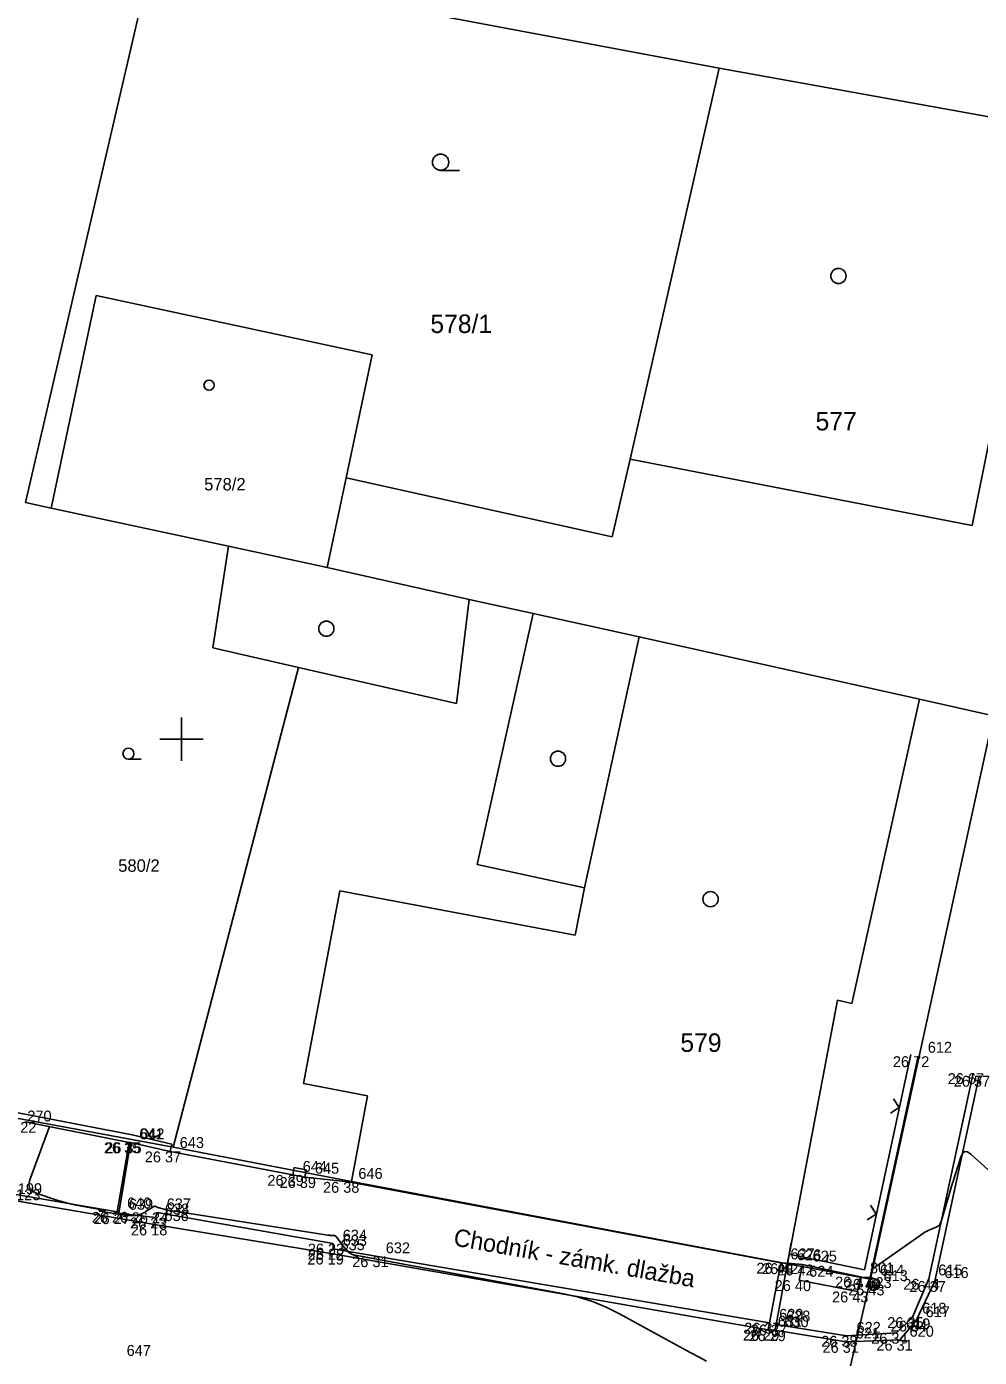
# Model space of a CAD drawing. Extents: x -702257 to -701487, y -1009871 to -1008841.
# Drawn here: x -701728.56 to -701706.64, y -1009389.21 to -1009358.61 of the extents above; entities that cross this region are included whole.
import ezdxf

# ---------------------------------------------------------------- set-up
doc = ezdxf.new("R2010")
doc.units = 0
for name, color, linetype in [('Ex_Minor Contours', 7, 'Continuous'), ('Z_body', 7, 'Continuous'), ('Z_body_cisla', 7, 'Continuous'), ('Z_body_vysky_redukovane', 7, 'Continuous'), ('Z_budova', 7, 'Continuous'), ('Z_hektometricka_sit', 7, 'Continuous'), ('Z_katastr_cisla_pozemkova', 7, 'Continuous'), ('Z_katastr_cisla_stavebni', 7, 'Continuous'), ('Z_katastr_hranice', 7, 'Continuous'), ('Z_katastr_vnitrni_kresba', 7, 'Continuous'), ('Z_katastr_znacky_budov', 7, 'Continuous'), ('Z_katastr_znacky_kultur', 7, 'Continuous'), ('Z_komunikace', 7, 'Continuous'), ('Z_obruba', 7, 'Continuous'), ('Z_pilire', 7, 'Continuous'), ('Z_ploty', 7, 'Continuous'), ('Z_ploty_znacky', 7, 'Continuous'), ('Z_popisy', 7, 'Continuous'), ('Z_sloupy', 7, 'Continuous'), ('Z_vstupy', 7, 'Continuous'), ('Z_zlabek', 7, 'Continuous')]:
    doc.layers.add(name, color=color, linetype=linetype)

# ---------------------------------------------------------------- blocks, each defined once
blk = doc.blocks.new('POINT_DISPLAY')
blk.add_line((0, 0), (0, 0))
blk = doc.blocks.new('Z210')
blk.add_line((0, 0), (0, 0.17))
blk = doc.blocks.new('Z212')
for p, q in [((-0.17, 0.17), (0, 0)), ((0, 0), (0.17, 0.17))]:
    blk.add_line(p, q)
blk = doc.blocks.new('Z601')
for p, q in [((-0.13, 0.03), (-0.1, 0.08)), ((-0.13, -0.03), (-0.13, 0.03)), ((-0.1, 0.08), (-0.08, 0.1)), ((-0.08, 0.1), (-0.03, 0.13)), ((-0.08, 0.05), (-0.08, -0.05)), ((-0.03, 0.13), (0.03, 0.13)), ((-0.03, -0.08), (-0.03, 0.08)), ((-0.03, 0.08), (0.03, 0.08)), ((0.03, 0.13), (0.08, 0.1)), ((0.03, 0.08), (0.03, -0.08)), ((0.08, 0.1), (0.1, 0.08)), ((0.08, -0.05), (0.08, 0.05)), ((0.1, 0.08), (0.13, 0.03)), ((0.13, 0.03), (0.13, -0.03)), ((-0.1, -0.08), (-0.13, -0.03)), ((-0.08, -0.1), (-0.1, -0.08)), ((-0.08, -0.05), (-0.03, -0.08)), ((-0.03, -0.13), (-0.08, -0.1)), ((0.03, -0.13), (-0.03, -0.13)), ((0.03, -0.08), (0.08, -0.05)), ((0.08, -0.1), (0.03, -0.13)), ((0.1, -0.08), (0.08, -0.1)), ((0.13, -0.03), (0.1, -0.08))]:
    blk.add_line(p, q)

msp = doc.modelspace()

# ---------------------------------------------------------------- linework, layer by layer
at = {"layer": 'Ex_Minor Contours'}
for points in [[(-701712.923, -1009389.301), (-701713.104, -1009389.206), (-701713.284, -1009389.11), (-701713.463, -1009389.012), (-701714.919, -1009388.212), (-701715.226, -1009388.059), (-701715.542, -1009387.932), (-701715.868, -1009387.83), (-701716.202, -1009387.755), (-701721.005, -1009386.867), (-701721.025, -1009386.863), (-701721.044, -1009386.857), (-701721.062, -1009386.849), (-701721.08, -1009386.839), (-701721.155, -1009386.794), (-701721.169, -1009386.785), (-701721.181, -1009386.774), (-701721.193, -1009386.763), (-701721.204, -1009386.751), (-701721.245, -1009386.699), (-701721.255, -1009386.685), (-701721.265, -1009386.672), (-701721.275, -1009386.659), (-701721.285, -1009386.646), (-701721.444, -1009386.436), (-701721.454, -1009386.425), (-701721.467, -1009386.417), (-701721.48, -1009386.412), (-701721.495, -1009386.41), (-701721.582, -1009386.409), (-701721.591, -1009386.408), (-701721.6, -1009386.407), (-701721.626, -1009386.403), (-701721.635, -1009386.401), (-701725.305, -1009385.83), (-701725.328, -1009385.826), (-701725.352, -1009385.821), (-701725.375, -1009385.816), (-701725.398, -1009385.81), (-701725.516, -1009385.778), (-701725.526, -1009385.775), (-701725.537, -1009385.771), (-701725.547, -1009385.767), (-701725.557, -1009385.763), (-701725.596, -1009385.743), (-701725.606, -1009385.74), (-701725.615, -1009385.739), (-701725.625, -1009385.741), (-701725.634, -1009385.745), (-701725.816, -1009385.863), (-701725.835, -1009385.874), (-701725.854, -1009385.885), (-701725.874, -1009385.894), (-701725.895, -1009385.903), (-701725.978, -1009385.934), (-701725.999, -1009385.941), (-701726.021, -1009385.946), (-701726.042, -1009385.95), (-701726.065, -1009385.951), (-701726.198, -1009385.956), (-701726.228, -1009385.956), (-701726.258, -1009385.955), (-701726.287, -1009385.952), (-701726.316, -1009385.948), (-701726.878, -1009385.85), (-701726.894, -1009385.846), (-701726.9, -1009385.844), (-701726.894, -1009385.842), (-701726.877, -1009385.842), (-701726.788, -1009385.841), (-701726.771, -1009385.841), (-701726.765, -1009385.839), (-701726.771, -1009385.836), (-701726.787, -1009385.833), (-701727.42, -1009385.713), (-701727.532, -1009385.69), (-701727.643, -1009385.663), (-701727.753, -1009385.632), (-701727.863, -1009385.597), (-701728.341, -1009385.438), (-701728.437, -1009385.39), (-701728.494, -1009385.323), (-701728.511, -1009385.237), (-701728.488, -1009385.131), (-701728.038, -1009383.908)], [(-701706.207, -1009385.118), (-701706.84, -1009384.544), (-701706.917, -1009384.491), (-701706.982, -1009384.484), (-701707.034, -1009384.523), (-701707.074, -1009384.608), (-701707.208, -1009385.039), (-701707.241, -1009385.147), (-701707.274, -1009385.255), (-701707.306, -1009385.363), (-701707.338, -1009385.471), (-701707.52, -1009386.093), (-701707.535, -1009386.132), (-701707.558, -1009386.164), (-701707.587, -1009386.19), (-701707.623, -1009386.21), (-701707.782, -1009386.279), (-701707.821, -1009386.297), (-701707.859, -1009386.317), (-701707.896, -1009386.339), (-701707.932, -1009386.362), (-701709.112, -1009387.187)]]:
    msp.add_lwpolyline(points, dxfattribs=at)
at = {"layer": 'Z_budova'}
for p, q in [((-701711.21, -1009387.04), (-701721.16, -1009385.18)), ((-701710.97, -1009386.58), (-701711.06, -1009387.05)), ((-701711.06, -1009387.05), (-701711.21, -1009387.04))]:
    msp.add_line(p, q, dxfattribs=at)
at = {"layer": 'Z_hektometricka_sit'}
for p, q in [((-701725, -1009374.5), (-701725, -1009375.5)), ((-701725, -1009374.5), (-701725, -1009375.5)), ((-701725, -1009374.5), (-701725, -1009375.5)), ((-701725.5, -1009375), (-701724.5, -1009375)), ((-701725.5, -1009375), (-701724.5, -1009375)), ((-701725.5, -1009375), (-701724.5, -1009375))]:
    msp.add_line(p, q, dxfattribs=at)
at = {"layer": 'Z_katastr_hranice'}
for p, q in [((-701728.59, -1009369.56), (-701725.71, -1009357.15)), ((-701720.37, -1009358.12), (-701712.63, -1009359.57)), ((-701712.63, -1009359.57), (-701714.68, -1009368.56)), ((-701712.63, -1009359.57), (-701705.18, -1009360.91)), ((-701728, -1009369.69), (-701726.96, -1009364.8)), ((-701726.96, -1009364.8), (-701720.61, -1009366.16)), ((-701720.61, -1009366.16), (-701721.21, -1009368.99)), ((-701714.68, -1009368.56), (-701715.09, -1009370.35)), ((-701721.21, -1009368.99), (-701721.65, -1009371.05)), ((-701715.09, -1009370.35), (-701721.21, -1009368.99)), ((-701728.59, -1009369.56), (-701728, -1009369.69)), ((-701723.92, -1009370.56), (-701728, -1009369.69)), ((-701723.92, -1009370.56), (-701724.28, -1009372.9)), ((-701721.65, -1009371.05), (-701723.92, -1009370.56)), ((-701721.65, -1009371.05), (-701718.38, -1009371.79)), ((-701718.38, -1009371.79), (-701716.91, -1009372.11)), ((-701716.91, -1009372.11), (-701714.47, -1009372.65)), ((-701714.47, -1009372.65), (-701708.02, -1009374.08)), ((-701724.28, -1009372.9), (-701722.31, -1009373.35)), ((-701722.31, -1009373.35), (-701725.19, -1009384.38)), ((-701708.02, -1009374.08), (-701706.32, -1009374.46)), ((-701709.15, -1009387.42), (-701706.32, -1009374.46)), ((-701731.72, -1009383.17), (-701725.19, -1009384.38)), ((-701725.19, -1009384.38), (-701721.09, -1009385.17)), ((-701721.09, -1009385.17), (-701711.06, -1009387.06)), ((-701711.06, -1009387.06), (-701709.15, -1009387.42)), ((-701709.15, -1009387.42), (-701711.4, -1009397.2))]:
    msp.add_line(p, q, dxfattribs=at)
at = {"layer": 'Z_katastr_vnitrni_kresba'}
for p, q in [((-701706.81, -1009370.09), (-701705.82, -1009365.14)), ((-701714.68, -1009368.56), (-701706.81, -1009370.09)), ((-701718.38, -1009371.79), (-701718.67, -1009374.18)), ((-701718.2, -1009377.88), (-701716.91, -1009372.11)), ((-701714.47, -1009372.65), (-701715.73, -1009378.42)), ((-701718.67, -1009374.18), (-701722.31, -1009373.35)), ((-701708.02, -1009374.08), (-701709.58, -1009381.08)), ((-701715.73, -1009378.42), (-701718.2, -1009377.88)), ((-701715.94, -1009379.51), (-701715.73, -1009378.42)), ((-701721.36, -1009378.49), (-701722.19, -1009382.92)), ((-701721.36, -1009378.49), (-701715.94, -1009379.51)), ((-701709.91, -1009381), (-701711.06, -1009387.06)), ((-701709.58, -1009381.08), (-701709.91, -1009381)), ((-701722.19, -1009382.92), (-701720.72, -1009383.2)), ((-701720.72, -1009383.2), (-701721.09, -1009385.17))]:
    msp.add_line(p, q, dxfattribs=at)
at = {"layer": 'Z_katastr_znacky_budov'}
for centre, radius in [((-701709.887, -1009364.349), 0.175), ((-701724.365, -1009366.859), 0.117), ((-701721.667, -1009372.459), 0.175), ((-701716.337, -1009375.449), 0.175), ((-701712.827, -1009378.679), 0.175)]:
    msp.add_circle(centre, radius, dxfattribs=at)
at = {"layer": 'Z_katastr_znacky_kultur'}
for p, q in [((-701719.038, -1009361.92), (-701718.601, -1009361.92)), ((-701726.219, -1009375.46), (-701725.926, -1009375.46))]:
    msp.add_line(p, q, dxfattribs=at)
for centre, radius in [((-701719.038, -1009361.732), 0.187), ((-701726.219, -1009375.334), 0.126)]:
    msp.add_circle(centre, radius, dxfattribs=at)
at = {"layer": 'Z_komunikace'}
for p, q in [((-701706.65, -1009382.74), (-701707.67, -1009387.46)), ((-701728.85, -1009385.61), (-701725.62, -1009386.16)), ((-701721.56, -1009386.83), (-701725.62, -1009386.16)), ((-701711.5, -1009388.58), (-701721.56, -1009386.83)), ((-701707.67, -1009387.46), (-701708.1, -1009388.37)), ((-701708.1, -1009388.37), (-701708.47, -1009388.81)), ((-701711.35, -1009388.59), (-701711.5, -1009388.58)), ((-701709.71, -1009388.86), (-701711.35, -1009388.59)), ((-701708.47, -1009388.81), (-701709.71, -1009388.86))]:
    msp.add_line(p, q, dxfattribs=at)
at = {"layer": 'Z_obruba'}
for p, q in [((-701706.79, -1009382.68), (-701707.81, -1009387.41)), ((-701726.2, -1009384.27), (-701726.48, -1009385.87)), ((-701726.44, -1009385.9), (-701726.17, -1009384.27)), ((-701728.81, -1009385.47), (-701726.48, -1009385.87)), ((-701726.44, -1009385.9), (-701726.48, -1009385.87)), ((-701725.6, -1009386), (-701726.44, -1009385.9)), ((-701725.56, -1009385.88), (-701725.6, -1009386)), ((-701721.51, -1009386.6), (-701725.56, -1009385.88)), ((-701721.51, -1009386.72), (-701721.51, -1009386.6)), ((-701720.53, -1009386.89), (-701721.51, -1009386.72)), ((-701711.47, -1009388.42), (-701720.53, -1009386.89)), ((-701707.81, -1009387.41), (-701708.18, -1009388.29)), ((-701709.7, -1009388.72), (-701711.32, -1009388.46)), ((-701708.18, -1009388.29), (-701708.55, -1009388.65)), ((-701708.55, -1009388.65), (-701709.7, -1009388.72))]:
    msp.add_line(p, q, dxfattribs=at)
at = {"layer": 'Z_pilire'}
for p, q in [((-701710.79, -1009387.44), (-701710.71, -1009387.08)), ((-701710.79, -1009387.44), (-701709.45, -1009387.7)), ((-701709.45, -1009387.7), (-701709.38, -1009387.36))]:
    msp.add_line(p, q, dxfattribs=at)
at = {"layer": 'Z_ploty'}
for p, q in [((-701728.558, -1009383.628), (-701740.738, -1009381.358)), ((-701708.22, -1009382.25), (-701709.29, -1009387.2)), ((-701708.05, -1009382.29), (-701709.16, -1009387.41)), ((-701728.558, -1009383.628), (-701726.13, -1009384.1)), ((-701728.59, -1009383.8), (-701726.2, -1009384.27)), ((-701726.2, -1009384.27), (-701726.17, -1009384.27)), ((-701726.17, -1009384.27), (-701725.26, -1009384.48)), ((-701726.13, -1009384.1), (-701725.22, -1009384.31)), ((-701725.26, -1009384.48), (-701725.22, -1009384.31)), ((-701722.44, -1009385.02), (-701722.41, -1009384.85)), ((-701722.41, -1009384.85), (-701722.13, -1009384.9)), ((-701722.44, -1009385.02), (-701722.16, -1009385.07)), ((-701722.16, -1009385.07), (-701722.13, -1009384.9)), ((-701711.02, -1009386.84), (-701709.29, -1009387.2)), ((-701711.06, -1009387.05), (-701710.71, -1009387.08)), ((-701710.71, -1009387.08), (-701709.38, -1009387.36)), ((-701709.38, -1009387.36), (-701709.16, -1009387.41))]:
    msp.add_line(p, q, dxfattribs=at)
at = {"layer": 'Z_vstupy'}
for p, q in [((-701725.26, -1009384.48), (-701722.44, -1009385.02)), ((-701722.16, -1009385.07), (-701721.16, -1009385.18))]:
    msp.add_line(p, q, dxfattribs=at)
at = {"layer": 'Z_zlabek'}
for p, q in [((-701711.47, -1009388.42), (-701711.21, -1009387.04)), ((-701711.06, -1009387.05), (-701711.32, -1009388.46)), ((-701711.5, -1009388.58), (-701711.47, -1009388.42)), ((-701711.32, -1009388.46), (-701711.35, -1009388.59))]:
    msp.add_line(p, q, dxfattribs=at)

# ---------------------------------------------------------------- block references
at = {"layer": 'Z_body'}
for p in [(-701708.05, -1009382.29), (-701706.79, -1009382.68), (-701706.65, -1009382.74), (-701726.2, -1009384.27), (-701726.17, -1009384.27), (-701725.26, -1009384.48), (-701722.44, -1009385.02), (-701722.16, -1009385.07), (-701721.16, -1009385.18), (-701726.48, -1009385.87), (-701726.44, -1009385.9), (-701725.6, -1009386), (-701725.56, -1009385.88), (-701725.62, -1009386.16), (-701721.51, -1009386.6), (-701721.51, -1009386.72), (-701721.56, -1009386.83), (-701720.53, -1009386.89), (-701711.21, -1009387.04), (-701711.06, -1009387.05), (-701710.71, -1009387.08), (-701710.79, -1009387.44), (-701709.38, -1009387.36), (-701709.16, -1009387.41), (-701709.08, -1009387.54), (-701707.81, -1009387.41), (-701707.67, -1009387.46), (-701709.45, -1009387.7), (-701711.47, -1009388.42), (-701711.32, -1009388.46), (-701708.18, -1009388.29), (-701708.1, -1009388.37), (-701711.5, -1009388.58), (-701711.35, -1009388.59), (-701709.71, -1009388.86), (-701709.7, -1009388.72), (-701708.55, -1009388.65), (-701708.47, -1009388.81)]:
    msp.add_blockref('POINT_DISPLAY', p, dxfattribs=at)
at = {"layer": 'Z_ploty_znacky'}
for name, p, rotation in [('Z212', (-701708.49, -1009383.47), 77.8), ('Z212', (-701725.68, -1009384.2), -13.00000000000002), ('Z212', (-701709.02, -1009385.92), 77.8), ('Z210', (-701710.16, -1009387.02), -11.899999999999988)]:
    msp.add_blockref(name, p, dxfattribs=dict(at, rotation=rotation))
at = {"layer": 'Z_sloupy'}
msp.add_blockref('Z601', (-701709.08, -1009387.54), dxfattribs=at)

# ---------------------------------------------------------------- texts
at = {"layer": 'Z_body_cisla'}
for s, p in [('612', (-701707.83, -1009382.21)), ('270', (-701728.545, -1009383.79)), ('641', (-701725.97, -1009384.2)), ('642', (-701725.95, -1009384.2)), ('643', (-701725.04, -1009384.4)), ('644', (-701722.21, -1009384.95)), ('645', (-701721.93, -1009384.99)), ('646', (-701720.93, -1009385.11)), ('123', (-701728.805, -1009385.6)), ('199', (-701728.765, -1009385.46)), ('640', (-701726.25, -1009385.79)), ('639', (-701726.21, -1009385.82)), ('638', (-701725.38, -1009385.93)), ('637', (-701725.34, -1009385.81)), ('636', (-701725.39, -1009386.08)), ('634', (-701721.29, -1009386.53)), ('633', (-701721.29, -1009386.65)), ('635', (-701721.34, -1009386.75)), ('632', (-701720.3, -1009386.82)), ('627', (-701710.99, -1009386.96)), ('626', (-701710.84, -1009386.98)), ('625', (-701710.48, -1009387.01)), ('801', (-701709.16, -1009387.28)), ('624', (-701710.56, -1009387.36)), ('614', (-701708.93, -1009387.33)), ('613', (-701708.85, -1009387.46)), ('615', (-701707.59, -1009387.33)), ('616', (-701707.45, -1009387.39)), ('623', (-701709.22, -1009387.62)), ('631', (-701711.28, -1009388.51)), ('629', (-701711.25, -1009388.35)), ('628', (-701711.09, -1009388.39)), ('618', (-701707.96, -1009388.21)), ('617', (-701707.88, -1009388.29)), ('630', (-701711.13, -1009388.52)), ('621', (-701709.49, -1009388.78)), ('622', (-701709.47, -1009388.65)), ('619', (-701708.33, -1009388.57)), ('620', (-701708.25, -1009388.74)), ('647', (-701726.26, -1009389.18))]:
    msp.add_text(s, height=0.25, dxfattribs=at).set_placement(p)
at = {"layer": 'Z_body_vysky_redukovane'}
for s, p in [('26 72', (-701708.633, -1009382.54)), ('26 67', (-701707.373, -1009382.93)), ('26 57', (-701707.233, -1009382.99)), ('26 22', (-701729.173, -1009384.05)), ('26 35', (-701726.783, -1009384.52)), ('26 35', (-701726.753, -1009384.52)), ('26 37', (-701725.843, -1009384.73)), ('26 39', (-701723.023, -1009385.27)), ('26 39', (-701722.743, -1009385.32)), ('26 38', (-701721.743, -1009385.43)), ('26 26', (-701727.063, -1009386.12)), ('26 27', (-701727.023, -1009386.15)), ('26 23', (-701726.183, -1009386.25)), ('26 24', (-701726.143, -1009386.13)), ('26 18', (-701726.162, -1009386.41)), ('26 23', (-701722.093, -1009386.85)), ('26 22', (-701722.093, -1009386.97)), ('26 19', (-701722.102, -1009387.08)), ('26 31', (-701721.072, -1009387.14)), ('26 40', (-701711.773, -1009387.29)), ('26 42', (-701711.643, -1009387.3)), ('26 42', (-701711.293, -1009387.33)), ('26 40', (-701711.353, -1009387.69)), ('26 47', (-701709.963, -1009387.61)), ('26 49', (-701709.743, -1009387.66)), ('26 43', (-701709.663, -1009387.79)), ('26 44', (-701708.393, -1009387.66)), ('26 37', (-701708.253, -1009387.71)), ('26 43', (-701710.033, -1009387.95)), ('26 37', (-701712.053, -1009388.67)), ('26 37', (-701711.903, -1009388.71)), ('26 35', (-701708.763, -1009388.54)), ('26 34', (-701708.683, -1009388.62)), ('26 29', (-701712.083, -1009388.83)), ('26 29', (-701711.933, -1009388.84)), ('26 38', (-701710.283, -1009388.97)), ('26 31', (-701710.252, -1009389.11)), ('26 34', (-701709.133, -1009388.9)), ('26 31', (-701709.012, -1009389.06))]:
    msp.add_text(s, height=0.25, dxfattribs=at).set_placement(p)
at = {"layer": 'Z_katastr_cisla_pozemkova'}
for s, height, p in [('578/1', 0.425, (-701719.274, -1009365.66)), ('580/2', 0.285, (-701726.455, -1009378.049))]:
    msp.add_text(s, height=height, dxfattribs=at).set_placement(p)
at = {"layer": 'Z_katastr_cisla_stavebni'}
for s, height, p in [('577', 0.425, (-701710.413, -1009367.9)), ('578/2', 0.285, (-701724.478, -1009369.279)), ('579', 0.425, (-701713.523, -1009382.19))]:
    msp.add_text(s, height=height, dxfattribs=at).set_placement(p)
at = {"layer": 'Z_popisy'}
msp.add_text('Chodník - zámk. dlažba', height=0.4, rotation=350.1, dxfattribs=at).set_placement((-701718.76, -1009386.64))

doc.saveas('drawing.dxf')
